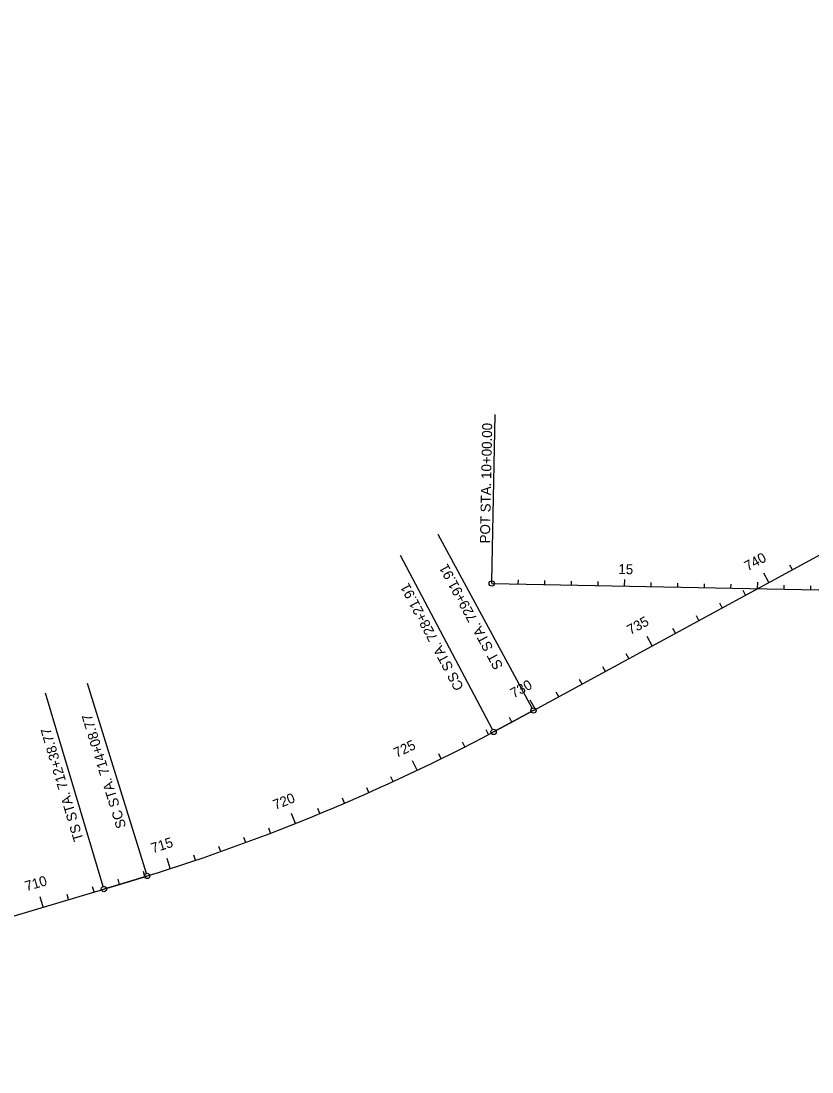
# Model space of a CAD drawing. Extents: x 1280727 to 1452510, y 526233 to 601451.
# Drawn here: x 1335021 to 1337997, y 549727 to 553677 of the extents above; entities that cross this region are included whole.
import ezdxf

# ---------------------------------------------------------------- set-up
doc = ezdxf.new("R2010")
doc.units = 0
for name, color, linetype in [('RW_X_CL', 7, 'Continuous'), ('RW_X_CL_500_Stations', 7, 'Continuous'), ('SH_Text', 7, 'Continuous')]:
    doc.layers.add(name, color=color, linetype=linetype)

msp = doc.modelspace()

# ---------------------------------------------------------------- linework, layer by layer
at = {"layer": 'RW_X_CL'}
for p, q in [((1336948.9, 551085.5), (1341722.2, 553677)), ((1336792, 551562.9), (1338791.6, 551523.4)), ((1333030, 549726.6), (1335333.3, 550414.3))]:
    msp.add_line(p, q, dxfattribs=at)
msp.add_arc((1333229.1, 557758.9), 7639.4, 287.26186, 297.86035, dxfattribs=at)
for points in [[(1336948.9, 551085.5), (1336946.8, 551084.4), (1336944.8, 551083.4), (1336942.8, 551082.3), (1336940.8, 551081.2), (1336938.8, 551080.1), (1336936.7, 551079), (1336934.7, 551077.9), (1336932.7, 551076.8), (1336930.7, 551075.7), (1336928.7, 551074.6), (1336926.6, 551073.5), (1336924.6, 551072.4), (1336922.6, 551071.3), (1336920.6, 551070.2), (1336918.6, 551069.1), (1336916.5, 551068), (1336914.5, 551066.9), (1336912.5, 551065.8), (1336910.5, 551064.7), (1336908.5, 551063.6), (1336906.4, 551062.5), (1336904.4, 551061.4), (1336902.4, 551060.4), (1336900.4, 551059.3), (1336898.4, 551058.2), (1336896.3, 551057.1), (1336894.3, 551056), (1336892.3, 551054.9), (1336890.3, 551053.8), (1336888.3, 551052.7), (1336886.2, 551051.6), (1336884.2, 551050.5), (1336882.2, 551049.4), (1336880.2, 551048.3), (1336878.2, 551047.2), (1336876.1, 551046.1), (1336874.1, 551045.1), (1336872.1, 551044), (1336870.1, 551042.9), (1336868, 551041.8), (1336866, 551040.7), (1336864, 551039.6), (1336862, 551038.5), (1336860, 551037.4), (1336857.9, 551036.3), (1336855.9, 551035.3), (1336853.9, 551034.2), (1336851.9, 551033.1), (1336849.8, 551032), (1336847.8, 551030.9), (1336845.8, 551029.8), (1336843.8, 551028.7), (1336841.7, 551027.7), (1336839.7, 551026.6), (1336837.7, 551025.5), (1336835.7, 551024.4), (1336833.6, 551023.3), (1336831.6, 551022.2), (1336829.6, 551021.2), (1336827.6, 551020.1), (1336825.5, 551019), (1336823.5, 551017.9), (1336821.5, 551016.8), (1336819.4, 551015.8), (1336817.4, 551014.7), (1336815.4, 551013.6), (1336813.4, 551012.5), (1336811.3, 551011.4), (1336809.3, 551010.4), (1336807.3, 551009.3), (1336805.2, 551008.2), (1336803.2, 551007.1), (1336801.2, 551006.1), (1336799.1, 551005)], [(1335333.3, 550414.3), (1335335.5, 550415), (1335337.7, 550415.7), (1335339.9, 550416.3), (1335342.1, 550417), (1335344.3, 550417.6), (1335346.5, 550418.3), (1335348.7, 550418.9), (1335350.9, 550419.6), (1335353.1, 550420.3), (1335355.3, 550420.9), (1335357.5, 550421.6), (1335359.7, 550422.2), (1335361.9, 550422.9), (1335364.1, 550423.6), (1335366.3, 550424.2), (1335368.5, 550424.9), (1335370.7, 550425.5), (1335372.9, 550426.2), (1335375.1, 550426.8), (1335377.3, 550427.5), (1335379.5, 550428.2), (1335381.7, 550428.8), (1335383.9, 550429.5), (1335386.1, 550430.1), (1335388.3, 550430.8), (1335390.5, 550431.5), (1335392.7, 550432.1), (1335394.9, 550432.8), (1335397.1, 550433.4), (1335399.3, 550434.1), (1335401.5, 550434.8), (1335403.7, 550435.4), (1335405.9, 550436.1), (1335408.1, 550436.8), (1335410.3, 550437.4), (1335412.5, 550438.1), (1335414.7, 550438.7), (1335416.9, 550439.4), (1335419.1, 550440.1), (1335421.3, 550440.7), (1335423.5, 550441.4), (1335425.7, 550442.1), (1335427.9, 550442.7), (1335430.1, 550443.4), (1335432.3, 550444.1), (1335434.5, 550444.7), (1335436.7, 550445.4), (1335438.9, 550446.1), (1335441.1, 550446.7), (1335443.3, 550447.4), (1335445.5, 550448.1), (1335447.7, 550448.7), (1335449.9, 550449.4), (1335452.1, 550450.1), (1335454.3, 550450.7), (1335456.5, 550451.4), (1335458.7, 550452.1), (1335460.9, 550452.8), (1335463.1, 550453.4), (1335465.3, 550454.1), (1335467.5, 550454.8), (1335469.7, 550455.5), (1335471.9, 550456.1), (1335474.1, 550456.8), (1335476.3, 550457.5), (1335478.5, 550458.2), (1335480.7, 550458.8), (1335482.9, 550459.5), (1335485.1, 550460.2), (1335487.2, 550460.9), (1335489.4, 550461.5), (1335491.6, 550462.2), (1335493.8, 550462.9), (1335496, 550463.6)]]:
    msp.add_spline(points, degree=3, dxfattribs=at)
at = {"layer": 'RW_X_CL_500_Stations'}
for p, q in [((1337834.8, 551566.5), (1337815.7, 551601.7)), ((1337922.7, 551614.2), (1337913.1, 551631.8)), ((1336792, 551562.9), (1336792.4, 551587.9)), ((1336891.9, 551561), (1336892.2, 551576)), ((1336991.9, 551559), (1336992.2, 551574)), ((1337091.9, 551557), (1337092.2, 551572)), ((1337191.9, 551555), (1337192.2, 551570)), ((1337291.9, 551553.1), (1337292.4, 551578)), ((1337391.8, 551551.1), (1337392.1, 551566.1)), ((1337491.8, 551549.1), (1337492.1, 551564.1)), ((1337591.8, 551547.1), (1337592.1, 551562.1)), ((1337691.8, 551545.1), (1337692.1, 551560.1)), ((1337791.8, 551543.2), (1337792.3, 551568.2)), ((1337746.9, 551518.8), (1337737.4, 551536.4)), ((1337891.7, 551541.2), (1337892, 551556.2)), ((1337991.7, 551539.2), (1337992, 551554.2)), ((1337659, 551471.1), (1337649.5, 551488.7)), ((1337571.1, 551423.4), (1337561.6, 551441)), ((1337395.4, 551328), (1337376.3, 551363.1)), ((1337483.3, 551375.7), (1337473.7, 551393.3)), ((1337307.5, 551280.3), (1337298, 551297.8)), ((1337219.6, 551232.5), (1337210.1, 551250.1)), ((1337131.7, 551184.8), (1337122.2, 551202.4)), ((1336956, 551089.4), (1336936.9, 551124.6)), ((1337043.8, 551137.1), (1337034.3, 551154.7)), ((1336868, 551041.8), (1336858.5, 551059.4)), ((1336779.8, 550994.8), (1336770.5, 551012.5)), ((1336690.9, 550948.9), (1336681.9, 550966.7)), ((1336511.5, 550860.6), (1336494.3, 550896.7)), ((1336601.5, 550904.2), (1336592.7, 550922.1)), ((1336420.9, 550818.2), (1336412.5, 550836.4)), ((1336329.8, 550777), (1336321.7, 550795.3)), ((1336238.1, 550737), (1336230.2, 550755.4)), ((1336053.3, 550660.7), (1336038.5, 550697.9)), ((1336145.9, 550698.3), (1336138.3, 550716.7)), ((1335960.1, 550624.3), (1335953, 550643)), ((1335772.4, 550555.3), (1335765.8, 550574.1)), ((1335866.5, 550589.2), (1335859.6, 550608)), ((1335677.9, 550522.6), (1335671.5, 550541.6)), ((1335583, 550491.2), (1335570.7, 550529.2)), ((1335392, 550431.9), (1335386.2, 550451)), ((1335487.6, 550461), (1335481.7, 550480.1)), ((1335296.2, 550403.3), (1335290.4, 550422.4)), ((1335104.5, 550346), (1335093.1, 550384.4)), ((1335200.3, 550374.6), (1335194.6, 550393.8))]:
    msp.add_line(p, q, dxfattribs=at)
at = {"layer": 'SH_Text'}
for p, q in [((1336792.1, 551570.4), (1336804.5, 552197.4)), ((1336944.1, 551094.3), (1336589.9, 551746.8)), ((1336794.5, 551013.8), (1336448.5, 551668.5)), ((1335493.1, 550473.1), (1335271.3, 551186.6)), ((1335330.4, 550423.9), (1335113.5, 551150.7))]:
    msp.add_line(p, q, dxfattribs=at)
for centre in [(1336792, 551562.9), (1336948.9, 551085.5), (1336799.1, 551005), (1335496, 550463.6), (1335333.3, 550414.3)]:
    msp.add_circle(centre, 10, dxfattribs=at)

# ---------------------------------------------------------------- texts
at = {"layer": 'RW_X_CL_500_Stations'}
for s, rotation, p in [('740', 28.4979, (1337754.9, 551608.5)), ('15', 358.8671, (1337267.8, 551598.5)), ('735', 28.4979, (1337313.4, 551368.8)), ('730', 28.4979, (1336874.4, 551130.5)), ('725', 25.4461, (1336434, 550906.8)), ('720', 21.696, (1335977.9, 550711.4)), ('715', 17.946, (1335517.1, 550548.6)), ('710', 16.6244, (1335042.3, 550405.7))]:
    msp.add_text(s, height=37.5, rotation=rotation, dxfattribs=at).set_placement(p)
at = {"layer": 'SH_Text'}
for s, rotation, p in [('POT STA. 10+00.00', 88.8671, (1336784.9, 551713.1)), ('ST STA. 729+91.91', 118.4979, (1336835.8, 551251.8)), ('CS STA. 728+21.91', 117.8604, (1336688, 551172.5)), ('SC STA. 714+08.77', 107.2619, (1335417.6, 550648.6)), ('TS STA. 712+38.77', 106.6244, (1335256.9, 550600.3))]:
    msp.add_text(s, height=37.5, rotation=rotation, dxfattribs=at).set_placement(p)

doc.saveas('drawing.dxf')
